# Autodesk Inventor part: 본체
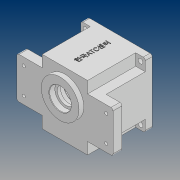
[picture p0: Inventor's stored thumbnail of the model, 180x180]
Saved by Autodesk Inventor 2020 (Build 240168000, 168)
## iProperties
Created: 2020-07
Part Number: 본체
Material: 일반
Document SubType Name: Modeling
Designer: PC312-
Density: 1 g/cm^3
Appearance: 기본값
Author: PC312-
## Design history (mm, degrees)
sketch "스케치1"
  geometry: L1 (-47, 47)-(47, 47); L2 (47, 47)-(47, -47); L3 (47, -47)-(-47, -47); L4 (-47, -47)-(-47, 47); L5 (-47, 47)-(47, -47); L6 (47, 47)-(-47, -47); 1 further point
  constraints: 12 end point, 2 midpoint, 2 parallel, 1 horizontal, 1 perpendicular
  dimensions: "d0" = 94 distance of L1.start L1.end; "d1" = 94 distance of L1.end L2.end
extrude "돌출1" new body sketch "스케치1" distance "d2" = 80; taper "d3" = 0 deg
sketch "스케치2"
  geometry: L1 (-70, 30)-(70, 30); L2 (70, 30)-(70, -30); L3 (70, -30)-(-70, -30); L4 (-70, -30)-(-70, 30); L5 (-70, 30)-(70, -30); L6 (70, 30)-(-70, -30); 1 further point
  constraints: 12 end point, 2 midpoint, 2 parallel, 1 horizontal, 1 perpendicular
  dimensions: "d4" = 60 distance of L1.end L2.end; "d5" = 140 distance of L2.end L3.end
extrude "돌출2" join sketch "스케치2" distance "d6" = 13; taper "d7" = 0 deg
sketch "스케치3"
  geometry: C1 r 27.5 at (0, 11); 1 further point
  constraints: 1 centre point, 1 vertical alignment
  dimensions: "d8" = 55 diameter of C1; "d9" = 11 distance of point (0, 0) C1.centre
extrude "돌출3" join sketch "스케치3" distance "d10" = 7; taper "d11" = 0 deg
sketch "스케치4"
  geometry: L1 (33, 47)-(47, 47); L2 (47, 47)-(47, 30); L3 (47, 30)-(33, 30); L4 (33, 30)-(33, 47); L5 (47, 30)-(47, 47) reference; L6 (47, 47)-(-47, 47) reference; L7 (-47, 47)-(-33, 47); L8 (-33, 47)-(-33, 30); L9 (-33, 30)-(-47, 30); L10 (-47, 30)-(-47, 47); L11 (-47, -47)-(-47, 47) reference; 3 further points
  constraints: 16 end point, 4 collinear, 4 parallel, 2 horizontal, 2 perpendicular
  dimensions: "d12" = 33 distance from line of point (0, 0) L4; "d13" = 30 distance from line of point (0, 0) L3; "d14" = 33 distance from line of point (0, 0) L8; "d15" = 30 distance from line of point (0, 0) L9
extrude "돌출4" cut sketch "스케치4" distance "d16" = 70; taper "d17" = 0 deg
node "스케치5"
sketch "스케치6"
  geometry: C1 r 43 at (0, 0); 1 further point
  constraints: 1 centre point, 1 coincident
  dimensions: "d23" = 86 diameter of C1
extrude "돌출5" cut sketch "스케치6" distance "d24" = 9; taper "d25" = 0 deg
sketch "스케치7"
  geometry: C1 r 40 at (0, 0); 1 further point
  constraints: 1 centre point, 1 coincident
  dimensions: "d26" = 80 diameter of C1
extrude "돌출6" cut sketch "스케치7" distance "d27" = 62; taper "d28" = 0 deg
sketch "스케치8"
  geometry: A1 r 21 centre (0, 11) between (8.978, -7.984) and (-8.978, -7.984); A2 r 15 centre (0, -20) between (-8.978, -7.984) and (8.978, -7.984); 1 further point
  constraints: 4 point on circle, 2 centre point, 2 vertical alignment
  dimensions: "d29" = 11 distance of point (0, 0) A1.centre; "d30" = 20 distance of A2.centre point (0, 0); "d31" = 42 diameter of A1; "d32" = 30 diameter of A2
extrude "돌출7" join sketch "스케치8" distance "d33" = 7; taper "d34" = 0 deg
sketch "스케치9"
  geometry: C1 r 27.5 at (0, 0) reference; C2 r 16 at (0, 0); 1 further point
  constraints: 1 centre point, 1 coincident
  dimensions: "d35" = 32 diameter of C2
extrude "돌출8" cut sketch "스케치9" distance "d36" = 8.3; taper "d37" = 0 deg
sketch "스케치10"
  geometry: C1 r 12.5 at (0, 0); C2 r 16 at (0, 0) reference; 1 further point
  constraints: 1 centre point, 1 coincident
  dimensions: "d38" = 25 diameter of C1
extrude "돌출9" cut sketch "스케치10" distance "d39" = 4.7; taper "d40" = 0 deg
sketch "스케치11"
  geometry: C1 r 12.5 at (0, 0) reference; C2 r 17.5 at (0, 0); 1 further point
  constraints: 1 centre point, 1 coincident
  dimensions: "d41" = 35 diameter of C2
extrude "돌출11" cut sketch "스케치11" distance "d44" = 10; taper "d45" = 0 deg
sketch "스케치12"
  geometry: C1 r 11 at (0, -20); A1 r 15 centre (0, -20) between (-8.978, -7.984) and (8.978, -7.984) reference; 1 further point
  constraints: 1 centre point, 1 coincident
  dimensions: "d46" = 22 diameter of C1
extrude "돌출12" cut sketch "스케치12" distance "d47" = 7; taper "d48" = 0 deg
sketch "스케치13"
  geometry: C1 r 11 at (0, 0) reference; C2 r 9.5 at (0, 0); 1 further point
  constraints: 1 centre point, 1 coincident
  dimensions: "d49" = 19 diameter of C2
extrude "돌출13" cut sketch "스케치13" distance "d50" = 3; taper "d51" = 0 deg
sketch "스케치14"
  geometry: A1 r 4 centre (36, 0) between (36.19, 3.995) and (36.19, -3.995); A2 r 36 centre (0, 0) between (36, 0) and (35.772, 4.045); A3 r 3 centre (36.333, 6.992) between (35.772, 4.045) and (39.279, 7.559); A4 r 40 centre (0, 0) between (39.279, 7.559) and (39.279, -7.559) reference; A5 r 3 centre (36.333, -6.992) between (39.279, -7.559) and (35.772, -4.045); 1 further point
  constraints: 13 point on circle, 4 centre point, 4 tangent, 1 coincident, 1 horizontal alignment
  dimensions: "d52" = 72 diameter of A2; "d53" = 8 diameter of A1; "d55" = 6 diameter of A3; "d56" = 6 diameter of A5
extrude "돌출14" join sketch "스케치14" stored distance "d57" = 3; taper "d58" = 0 deg
fillet "모깎기1" dims "d59" = 3
sketch "스케치16"
  geometry: C1 r 3.5 at (40, 40); A1 r 3 centre (44, 44) between (47, 44) and (44, 47) reference; 1 further point
  constraints: 1 centre point
  dimensions: "d62" = 7 diameter of C1; "d63" = 40 horizontal distance of point (0, 0) C1.centre; "d64" = 40 horizontal distance of C1.centre point (0, 0)
extrude "돌출15" cut sketch "스케치16" extent not by distance; stored distance "d65" = 0; taper "d66" = 0 deg
sketch "스케치17"
  geometry: 2 further points
  dimensions: "d73" = 19 vertical distance of point (0, 0) point (-60, 19); "d74" = 60 horizontal distance of point (-60, 19) point (0, 0)
hole "구멍1" sketch "스케치17" at (-60, 19) diameter "d75" = 4.5; stored, may be unused: countersink angle "d79" = 90 deg, drill point angle "d81" = 0 deg; dims "d76" = 7, "d77" = 10, "d78" = 5, "d80" = 15
sketch "스케치18"
  geometry: A1 r 4 centre (-36, 0) between (-36.19, -3.995) and (-36.19, 3.995) reference; 2 further points
  constraints: 1 coincident
hole "구멍2" sketch "스케치18" at (-36, 0) diameter "d91" = 3.242; stored, may be unused: countersink angle "d95" = 90 deg, drill point angle "d97" = 118 deg; dims "d92" = 7, "d93" = 10, "d94" = 5, "d96" = 9
chamfer "모따기2" distance "d98" = 1; stored, may be unused: second distance "d99" = 2, angle "d100" = 45 deg
fillet "모깎기2" dims "d107" = 3
node "작업 평면1"
sketch "스케치19"
  geometry: L1 (-11, 80)-(77, 80) reference; 2 further points
  constraints: 1 vertical alignment, 1 other
  dimensions: "d109" = 40 distance from line of L1 point (33, 40)
feature "엠보싱1" sketch "스케치19" dims "d110" = 0.5, "d111" = 0
chamfer "모따기5" distance "d112" = 0.8; stored, may be unused: second distance "d113" = 2, angle "d114" = 30 deg
fillet "모깎기3" dims "d115" = 3
chamfer "모따기6" distance "d116" = 1; stored, may be unused: second distance "d117" = 2, angle "d118" = 30 deg
node "솔리드1"
mirror "미러1"
mirror "미러2"
pattern_linear "직사각형 패턴1" dims "d69" = 80, "d72" = 80
pattern_linear "직사각형 패턴2" dims "d84" = 38, "d87" = 120
mirror "미러3"
feature "A9D066F2-1C7D-4E18-AEED-F7BC21143FA4" dims "d75" = 4.5, "d76" = 7, "d77" = 10, "d78" = 5, "d79" = 90 deg, "d80" = 15, "d81" = 0
other parameters: "d108" = 5
